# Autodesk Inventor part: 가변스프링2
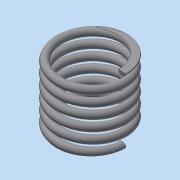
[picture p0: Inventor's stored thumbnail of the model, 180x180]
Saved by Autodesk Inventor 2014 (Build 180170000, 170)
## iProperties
Created: 2023-01
Part Number: 가변스프링2
Material: 스테인레스 스틸
Document SubType Name: Modeling
Designer: dg
Density: 8.08 g/cm^3
Appearance: 반연마
Mass: 7.93085 g
Surface Area: 20.0173 cm^2
Volume: 0.981541 cm^3
Author: dg
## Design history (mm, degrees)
sketch "스케치1"
  geometry: L1 (0, 0)-(0, 17); L2 (0, 0)-(8.5, 0); L3 (0, 17)-(8.5, 17); C1 r 1 at (8.5, 0)
  constraints: 6 end point, 1 centre point, 1 coincident, 1 parallel, 1 perpendicular, 1 vertical, 1 vertical alignment
  dimensions: "d0" = 17 distance of L1.start L1.end (derived); "d1" = 8.5 distance of L1.start L2.end; "d2" = 2 diameter of C1
feature "코일1" pitch "d3" = 10; turns "d5" = 6; dims "d4" = 17 (= d0), "d6" = 0, angle "d7" = 90 deg, angle "d8" = 90 deg, "d9" = 0, "d10" = 0
node "작업 평면1"
node "작업 평면2"
feature "분할1"
feature "분할2"
node "솔리드1"
other parameters: "d11" = 0, "d12" = 0
